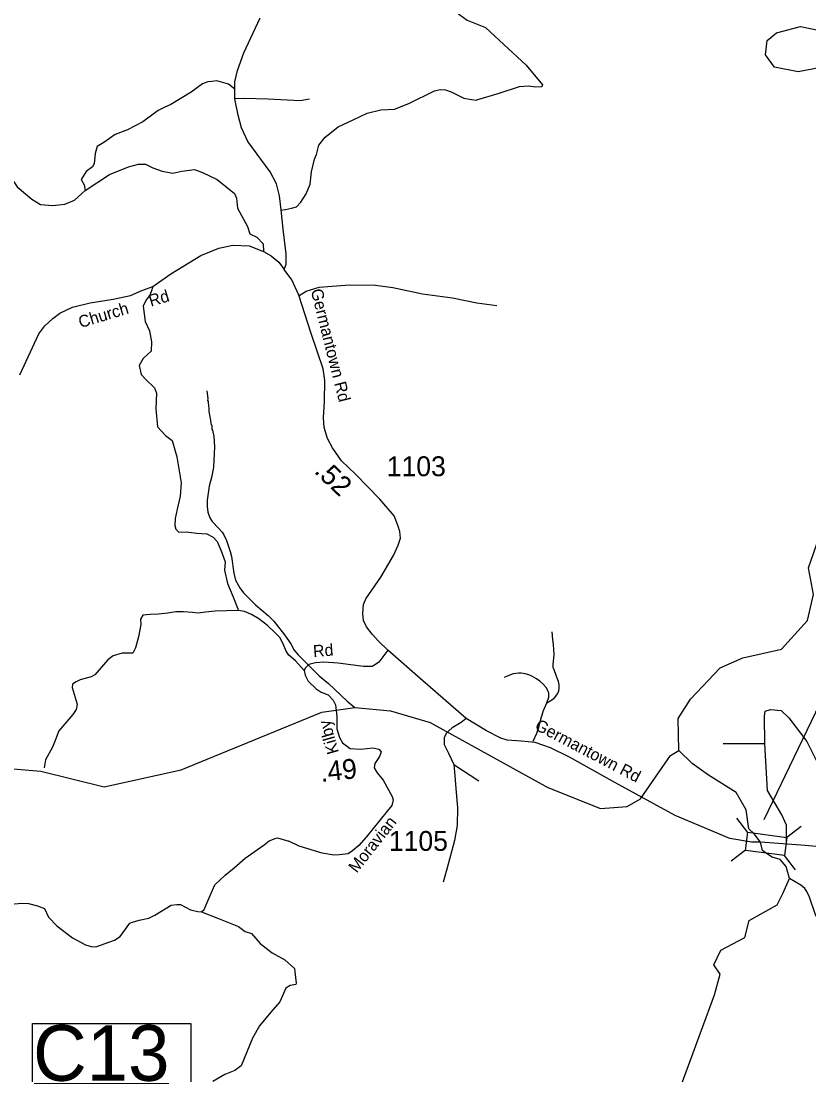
# Model space of a CAD drawing. Extents: x 1248089 to 1457196, y 820910 to 988753.
# Drawn here: x 1345980 to 1350937, y 860169 to 866798 of the extents above; entities that cross this region are included whole.
import ezdxf

# ---------------------------------------------------------------- set-up
doc = ezdxf.new("R2010")
doc.units = 0
for name, color, linetype in [('Exist Hydrographic Creek Single Shore', 7, 'Continuous'), ('Exist Hydrographic Misc Water Feature', 7, 'Continuous'), ('Exist Road Non-System Type 51', 7, 'Continuous'), ('Exist Road Primary NC Structure Culvert Number Label', 7, 'Continuous'), ('Exist Road Secondary Structure Standard Bridge CELL', 7, 'Continuous'), ('Exist Road Secondary Structure Standard Bridge Number Label', 7, 'Continuous'), ('Exist Road Secondary Type 51 Attributed', 7, 'Continuous'), ('Exist Road Secondary Type 51 Label', 7, 'Continuous'), ('Prop GRAU CAT1 Cell', 7, 'Continuous'), ('Prop Lane Lines', 7, 'Continuous')]:
    doc.layers.add(name, color=color, linetype=linetype)

msp = doc.modelspace()

# ---------------------------------------------------------------- linework, layer by layer
at = {"layer": 'Exist Hydrographic Creek Single Shore'}
for points in [[(1351155.2, 866532.2), (1350870.2, 866478.7), (1350721.2, 866508.1), (1350664.2, 866584.8), (1350675.2, 866676.4), (1350734.2, 866724.5), (1350885.2, 866764.1), (1351109.2, 866716.9)], [(1350118.3, 862209.9), (1350114.3, 862410.2), (1350191.3, 862533.3), (1350379.2, 862729.8), (1350522.2, 862792.6), (1350765.2, 862846.9), (1350928.2, 863027.4), (1350965.2, 863190.7), (1350935.2, 863358.9), (1351033.2, 863642.5), (1351023.3, 863951.2), (1351111.2, 864139.8), (1351122.2, 864632), (1351031.3, 865067.3)], [(1350632.1, 861633.8), (1350592.8, 861685), (1350559, 861717), (1350543.5, 861836.7), (1350479.8, 861945.6), (1350306.2, 862055.1), (1350202.8, 862128.4), (1350118.3, 862209.9)], [(1350010.2, 859554.6), (1350015.3, 859784.7), (1350342.3, 860672.3), (1350378.3, 860802.8), (1350338.3, 860862.8), (1350382.3, 860953.7), (1350534.2, 861032.8), (1350561.3, 861140.6), (1350738.3, 861238.7), (1350773.3, 861310.3), (1350816.1, 861404.3), (1350793.7, 861479.4), (1350757.2, 861524.2), (1350706.1, 861539.7), (1350669.5, 861561.6), (1350644.9, 861581.7), (1350632.1, 861633.8)]]:
    msp.add_lwpolyline(points, dxfattribs=at)
at = {"layer": 'Exist Hydrographic Misc Water Feature'}
for points in [[(1347148.6, 864472.9), (1347155.6, 864424.8), (1347153.2, 864410.9), (1347157.1, 864404.7), (1347158.4, 864372.8), (1347162.2, 864364.7), (1347161.7, 864342.6), (1347172.5, 864288.4), (1347173.9, 864266.3), (1347179.7, 864252.2), (1347181.2, 864230.2), (1347185, 864224.1), (1347192.1, 864183.9), (1347196.7, 864119.8), (1347189.7, 863992.1), (1347180.5, 863936.3), (1347163.1, 863872.6), (1347151.1, 863785), (1347150.2, 863745), (1347155.4, 863708.9), (1347166.6, 863672.6), (1347182, 863650.3), (1347225.1, 863607.2), (1347244.5, 863582.8), (1347256.2, 863566.5), (1347273.3, 863530.1), (1347295.7, 863461.6), (1347303, 863429.4), (1347318.7, 863325), (1347329.7, 863280.8), (1347356.6, 863232.2), (1347379.9, 863201.6), (1347454.2, 863125.8), (1347534.7, 863059.9), (1347569.9, 863023.1), (1347638, 862937.5), (1347676.7, 862880.6), (1347697.8, 862842), (1347723.2, 862811.5), (1347856.2, 862680.4), (1347915.1, 862630.9), (1348032.6, 862520.1), (1348080.4, 862480.3)], [(1343252.1, 861711), (1343773.1, 861858), (1344244.2, 862055.4), (1344470.1, 862109.9), (1344769.2, 862028.4), (1344958.1, 861932.7), (1345133.2, 861935.7), (1345929.2, 862093.7), (1346104.2, 862080.4), (1346502.2, 861980.5), (1346988.2, 862088.9), (1347872.2, 862451.9), (1348080.4, 862480.3), (1348305.2, 862459.6), (1348554.2, 862385.7), (1349295.2, 861976.8), (1349626.3, 861845.5), (1349793.3, 861858.5), (1349877.2, 861906.1), (1350067.2, 862178.1), (1350118.3, 862209.9)], [(1351511.8, 860340.9), (1351387.2, 860478.5), (1351340.2, 860521.7), (1351298.9, 860552.6), (1351247.9, 860599.8), (1351234.3, 860616.2), (1351211.2, 860656.7), (1351203.9, 860688.9), (1351177.2, 860745.5), (1351134.5, 860802.5), (1351111, 860827.1), (1351080.3, 860883.8), (1351076.7, 860899.9), (1351055.8, 860948.4), (1351030.6, 861069), (1350977, 861182.3), (1350941.5, 861287), (1350924.2, 861323.4), (1350910.7, 861341.8), (1350887.1, 861362.3), (1350816.1, 861404.3)]]:
    msp.add_lwpolyline(points, dxfattribs=at)
at = {"layer": 'Exist Road Non-System Type 51'}
msp.add_line((1350660.7, 862252.6), (1350398.6, 862252.3), dxfattribs=at)
for points in [[(1348355.8, 867250.9), (1348534.7, 867008.8), (1348648.8, 866904.8), (1348786.8, 866804.2), (1348902.7, 866758.2), (1349018.5, 866650.7), (1349158.2, 866519.5), (1349260.4, 866397.6), (1349257, 866383.9), (1349219.5, 866382.2), (1349171.8, 866389.1), (1349113.9, 866383.9), (1348986.1, 866341.3), (1348846.4, 866300.4)], [(1347325.4, 866369), (1347286, 866400.1), (1347211.6, 866421.8), (1347180.6, 866418.7), (1347155.7, 866415.6), (1347121.6, 866403.2), (1347050.3, 866350.5), (1346923.2, 866272.9), (1346879.8, 866254.3), (1346842.5, 866235.6), (1346746.4, 866164.3), (1346650.3, 866114.6), (1346572.7, 866083.6), (1346501.4, 866033.9), (1346458, 866009.1), (1346445.6, 865965.6), (1346439.4, 865900.5), (1346430.1, 865881.9), (1346389.8, 865850.8), (1346358.8, 865801.2), (1346377.4, 865767), (1346383.6, 865732.9)], [(1347613.1, 865608.2), (1347643.7, 865611.6), (1347681.2, 865621.9), (1347711.9, 865628.7), (1347740.8, 865659.4), (1347773.2, 865710.5), (1347798.8, 865771.9), (1347807.3, 865850.3), (1347826, 865928.7), (1347839.6, 865959.4), (1347853.3, 866017.4), (1347894.1, 866068.5), (1347975.9, 866131.6), (1348069.6, 866175.9), (1348158.2, 866218.6), (1348243.4, 866239), (1348328.6, 866244.1), (1348418.8, 866279.1), (1348580.7, 866359.2), (1348616.5, 866367.7), (1348650.5, 866366), (1348686.3, 866352.4), (1348766.4, 866313.2), (1348814.1, 866304.7), (1348846.4, 866300.4)], [(1345772.4, 866332.4), (1345735.2, 866195.9), (1345713.5, 866087.3), (1345722.8, 866037.6), (1345766.2, 865984.9), (1345859.2, 865898), (1345955.3, 865755.2), (1346048.4, 865677.6), (1346101.1, 865643.5), (1346178.6, 865637.3), (1346256.1, 865646.6), (1346315.1, 865671.4), (1346383.6, 865732.9)], [(1347325.2, 866309.8), (1347384.8, 866313.2), (1347534.7, 866308.1), (1347735.7, 866297.8), (1347795.3, 866308.1)], [(1346383.6, 865732.9), (1346535.5, 865832.2), (1346656.5, 865881.9), (1346718.5, 865897.4), (1346761.9, 865897.4), (1346808.4, 865875.6), (1346867.3, 865853.9), (1346935.6, 865841.5), (1346991.4, 865853.9), (1347072, 865863.2), (1347121.6, 865844.6), (1347214.7, 865801.2), (1347323.2, 865714.3), (1347335.6, 865683.2), (1347341.8, 865621.2), (1347403.8, 865506.4), (1347419.3, 865459.8), (1347462.8, 865438.1), (1347503.1, 865397.7), (1347505.1, 865348.1)], [(1346809.1, 865128.1), (1346797.8, 865093.9), (1346788.5, 865069.1), (1346766.8, 865044.2), (1346748.2, 865003.9), (1346760.6, 864907.7), (1346788.5, 864848.7), (1346800.9, 864780.5), (1346797.8, 864721.5), (1346776.1, 864699.8), (1346748.2, 864674.9), (1346723.4, 864631.5), (1346735.8, 864575.6), (1346763.7, 864544.6), (1346819.5, 864491.9), (1346832, 864457.7), (1346828.8, 864358.4), (1346838.2, 864246.7), (1346887.8, 864190.8), (1346931.2, 864159.8), (1346959.1, 864057.4), (1346987, 863892.9), (1346980.8, 863809.1), (1346962.2, 863728.4), (1346949.8, 863669.5), (1346946.7, 863626), (1346952.9, 863601.2), (1346971.5, 863582.6), (1347018, 863585.7), (1347086.2, 863576.4), (1347148.3, 863573.3), (1347188.6, 863551.6), (1347213.4, 863524.7), (1347238.2, 863466.7), (1347265.1, 863396.4), (1347260.9, 863344.7), (1347279.5, 863259.8), (1347312.6, 863181.2), (1347347.6, 863090.6)], [(1347728.9, 865071.2), (1347773.2, 865098.5), (1347855, 865124), (1348045.8, 865139.4), (1348211, 865136), (1348320, 865122.3), (1348505.7, 865081.4), (1348694.8, 865057.6), (1348848.1, 865025.2), (1348972.5, 865008.1)], [(1347347.6, 863090.6), (1347200.8, 863086.4), (1347140.9, 863080.2), (1347093.3, 863074), (1347058.2, 863078.1), (1347002.4, 863082.3), (1346952.7, 863082.3), (1346903.1, 863074), (1346845.2, 863067.8), (1346791.5, 863065.7), (1346746, 863061.6), (1346732.1, 863035.1), (1346734.2, 863002), (1346719.7, 862925.5), (1346699, 862855.1), (1346682.5, 862822), (1346616.3, 862822), (1346558.5, 862805.5), (1346525.4, 862780.7), (1346444.8, 862685.5), (1346419.9, 862673.1), (1346351.7, 862654.5), (1346326.9, 862642), (1346304.2, 862627.6), (1346302.1, 862606.9)], [(1347760.2, 862713.2), (1347707.3, 862774), (1347663.9, 862809.2), (1347647.4, 862834), (1347628.8, 862881.6), (1347608.1, 862920.9), (1347577.1, 862951.9), (1347529.5, 862995.4), (1347475.8, 863038.8), (1347430.3, 863065.7), (1347384.8, 863084.3), (1347347.6, 863090.6)], [(1349288.4, 862508.9), (1349318.8, 862528.3), (1349339.1, 862543.9), (1349355.6, 862565.6), (1349364, 862585.4), (1349366.4, 862603.4), (1349364.8, 862623.4), (1349361.2, 862643.5), (1349353.6, 862665.7), (1349345.9, 862681.8), (1349334.6, 862718.1), (1349328.9, 862732.2), (1349327.3, 862750.2), (1349329.7, 862770.2), (1349334.6, 862814.1), (1349333.1, 862842.2), (1349329.8, 862876.3), (1349326.5, 862908.4), (1349321.4, 862956.5)], [(1349288.4, 862508.9), (1349301.1, 862544.6), (1349301.5, 862560.7), (1349299.7, 862570.7), (1349294, 862586.8), (1349284.4, 862607), (1349264.8, 862627.4), (1349243.1, 862645.9), (1349223.4, 862660.3), (1349193.7, 862676.9), (1349175.9, 862685.2), (1349152, 862691.7), (1349126.1, 862696.3), (1349110.1, 862696.6), (1349075.9, 862691.3), (1349037.7, 862678), (1349019.4, 862668.4)], [(1346302.1, 862606.9), (1346333.6, 862501.9), (1346327.4, 862468.8), (1346304.6, 862435.7), (1346217.8, 862334.4), (1346195.1, 862272.3), (1346176.5, 862230.9), (1346133.1, 862150.2), (1346124.8, 862100.6)], [(1349201.5, 862268.5), (1349224.5, 862318.1), (1349237.3, 862353.8), (1349248.1, 862397.6), (1349254.6, 862421.5), (1349267.4, 862461.3), (1349288.4, 862508.9)], [(1350660.7, 862252.6), (1350657.9, 862426.4), (1350661.3, 862457.2), (1350695.4, 862467.4), (1350763.6, 862460.6), (1350811.4, 862416.2), (1350923.9, 862266), (1350999, 862115.8), (1351046.7, 862085.1), (1351125.2, 862095.3), (1351203.7, 862109), (1351640.3, 862126)], [(1348779.6, 862411.3), (1348748.3, 862385), (1348692.5, 862351.8), (1348671.8, 862333.2), (1348655.3, 862316.7), (1348642.9, 862289.8), (1348642.9, 862248.4), (1348669.8, 862192.5), (1348702.9, 862122.2)], [(1350797.1, 861621), (1350797.1, 861740.5), (1350766.4, 861805.4), (1350677.7, 861959), (1350660.7, 862252.6)], [(1348702.9, 862122.2), (1348709.1, 862049.8), (1348717.3, 861946.4), (1348725.6, 861851.2), (1348723.5, 861737.4), (1348707, 861644.3), (1348659.2, 861463.8), (1348636.4, 861381)], [(1348702.9, 862122.2), (1348860, 862018.8)], [(1347320.6, 861472.1), (1347388.9, 861532.1), (1347508.8, 861617), (1347541.8, 861641.8), (1347579.1, 861656.3), (1347593.5, 861660.4)], [(1347593.5, 861660.4), (1347664.9, 861639.4)], [(1345917.6, 861243.1), (1345981.7, 861249.3), (1346027.2, 861247.2), (1346083, 861232.7), (1346126.4, 861216.2), (1346153.3, 861162.4), (1346205, 861106.5), (1346304.2, 861032.1), (1346384.8, 860988.6), (1346420, 860976.2), (1346451, 860974.1), (1346566.8, 861017.6), (1346604, 861040.3), (1346663.9, 861123.1), (1346680.5, 861129.3), (1346723.9, 861141.7), (1346783.8, 861156.2), (1346821, 861174.8), (1346924.4, 861236.9), (1346959.6, 861241), (1346982.3, 861241), (1347046.4, 861207.9), (1347091.9, 861197.6), (1347116, 861194.9), (1347132.5, 861209.4), (1347169.7, 861298.4), (1347198.7, 861364.6), (1347264.8, 861426.6), (1347320.6, 861472.1)], [(1347116, 861194.9), (1347221.4, 861153.8), (1347347.5, 861102.1), (1347388.9, 861071), (1347430.2, 861058.6), (1347484, 860996.6), (1347560.5, 860936.6), (1347639, 860893.1), (1347701.1, 860839.3), (1347703.1, 860818.6), (1347711.4, 860746.2), (1347709.3, 860737.9), (1347672.1, 860731.7), (1347645.2, 860715.2), (1347608, 860628.3), (1347552.2, 860564.2), (1347479.8, 860477.3), (1347436.5, 860400.2), (1347364.2, 860226.4), (1347324.9, 860197.4), (1347262.9, 860172.6), (1347186.4, 860127.1)]]:
    msp.add_lwpolyline(points, dxfattribs=at)
at = {"layer": 'Exist Road Primary NC Structure Culvert Number Label'}
msp.add_lwpolyline([(1346051.9, 860492.4), (1347047.3, 860492.4), (1347047.3, 860112.5), (1346051.9, 860112.5)], close=True, dxfattribs=at)
at = {"layer": 'Exist Road Secondary Structure Standard Bridge CELL'}
for p, q in [((1350553.1, 861694.4), (1350484.4, 861784.3)), ((1350889, 861732.5), (1350799.1, 861663.7)), ((1350538.2, 861582.2), (1350448.3, 861513.4)), ((1350852.6, 861459), (1350783.8, 861548.9))]:
    msp.add_line(p, q, dxfattribs=at)
msp.add_lwpolyline([(1350783.8, 861548.9), (1350538.1, 861581.7), (1350553.4, 861696.4), (1350799.1, 861663.7)], close=True, dxfattribs=at)
at = {"layer": 'Exist Road Secondary Structure Standard Bridge Number Label'}
msp.add_line((1350655.5, 861776.7), (1351747.8, 864049.4), dxfattribs=at)
at = {"layer": 'Exist Road Secondary Type 51 Attributed'}
for points in [[(1347635.1, 865235.8), (1347648.6, 865268.2), (1347648.6, 865333), (1347629.7, 865489.7), (1347616, 865609.5), (1347605.4, 865697.8), (1347586.5, 865773.4), (1347546.7, 865850.3), (1347406.3, 866039.4), (1347365.8, 866125.9), (1347346.9, 866206.9), (1347325.4, 866309.6), (1347325.4, 866415), (1347341.6, 866487.9), (1347382, 866598.7), (1347483.4, 866818.8)], [(1345971.3, 864572.2), (1346092.2, 864830.1), (1346129.2, 864880.6), (1346179.7, 864926.1), (1346223.5, 864961.4), (1346302.6, 864998.5), (1346415.3, 865025.4), (1346558.3, 865049), (1346669.4, 865070.9), (1346740.1, 865102.9), (1346809.1, 865128.1), (1346921.8, 865207.3), (1347111.2, 865322.8), (1347224, 865369.9), (1347311.5, 865388.5), (1347414.1, 865383.4), (1347505.1, 865348.1), (1347553.8, 865321.1), (1347601.9, 865280.9), (1347635.1, 865235.8)], [(1348286.9, 862840.9), (1348229.1, 862896.8), (1348188.2, 862942), (1348153.8, 862987.2), (1348134.4, 863028.1), (1348130.1, 863071.2), (1348134.4, 863127.2), (1348149.5, 863163.8), (1348243.9, 863300.4), (1348323.5, 863436.1), (1348353.6, 863500.7), (1348366.5, 863545.9), (1348362.2, 863586.8), (1348353.6, 863621.3), (1348327.8, 863685.9), (1348237.8, 863790.6), (1348085, 863947.8), (1347996.8, 864031.8), (1347938.7, 864113.7), (1347908.6, 864171.8), (1347887.1, 864240.7), (1347882.8, 864303.2), (1347889.2, 864405.3), (1347891.4, 864536.7), (1347880.6, 864609.9), (1347805.3, 864831.7), (1347727.8, 865072.9), (1347682.7, 865169.8), (1347635.1, 865235.8)], [(1348286.9, 862840.9), (1348231.4, 862764.9), (1348209.9, 862749.9), (1348188.4, 862739.1), (1348134.6, 862739.1), (1347975.4, 862758.5), (1347885, 862764.9), (1347833.4, 862760.6), (1347790.3, 862749.9), (1347766.6, 862728.3), (1347760.2, 862713.2), (1347766.6, 862683.1), (1347786, 862646.5), (1347837.7, 862597), (1347867.8, 862577.6), (1347913, 862560.3), (1347943.1, 862525.9), (1347958.2, 862497.9), (1347966.8, 862424.7), (1347966.8, 862347.2), (1347984, 862291.2), (1348003.3, 862258.9), (1348050.7, 862222.2), (1348115.2, 862217.9), (1348194.9, 862226.6), (1348231.1, 862218.7), (1348246.2, 862201.5), (1348235.4, 862171.3), (1348205.3, 862128.2), (1348201, 862100.2), (1348220.4, 862070.1), (1348259.1, 862022.7), (1348315, 861921.5), (1348321.6, 861898.6), (1348313, 861864.2), (1348282.8, 861827.6), (1348151.6, 861663.9), (1348104.2, 861612.2), (1348065.5, 861577.8), (1348037.5, 861560.5), (1347981.6, 861554.1), (1347947.2, 861551.9), (1347874, 861564.8), (1347729.8, 861607.9), (1347664.9, 861639.4)], [(1350632.1, 861633.8), (1350575.5, 861632.5), (1350440.6, 861656.9), (1350095.8, 861800.6), (1349715.8, 862008.2), (1349431, 862167.6), (1349312.2, 862227.1), (1349215, 862260.8), (1349127.3, 862268.9), (1349038.2, 862275.7), (1348999.1, 862286.5), (1348909.2, 862332.9), (1348779.6, 862411.3), (1348508.3, 862649), (1348286.9, 862840.9)], [(1351118.1, 861593.4), (1350913, 861612.3), (1350632.1, 861633.8)]]:
    msp.add_lwpolyline(points, dxfattribs=at)

# ---------------------------------------------------------------- texts
at = {"layer": 'Exist Road Primary NC Structure Culvert Number Label'}
msp.add_text('C13', height=350, dxfattribs=at).set_placement((1346055.1, 860132.3))
at = {"layer": 'Exist Road Secondary Type 51 Label'}
for s, rotation, p in [(' Church     Rd', 16.84749, (1346327.2, 864858.2)), ('Germantown Rd', 284.1931, (1347801.9, 865103.9)), ('Rd', 4.31499, (1347819.8, 862797.1)), ('Kilby ', 105.88522, (1347980.8, 862198.7)), ('Germantown Rd', 332.36779, (1349206.7, 862344.8)), ('Moravian', 51.74313, (1348092.1, 861434.6))]:
    msp.add_text(s, height=75, rotation=rotation, dxfattribs=at).set_placement(p)
at = {"layer": 'Prop GRAU CAT1 Cell'}
for s, rotation, p in [('.52', 316.40946, (1347819, 863960.6)), ('.49', 6.17494, (1347868, 862011.6))]:
    msp.add_text(s, height=125, rotation=rotation, dxfattribs=at).set_placement(p)
at = {"layer": 'Prop Lane Lines'}
for s, p in [('1103', (1348280.8, 863935.3)), ('1105', (1348294.1, 861578.6))]:
    msp.add_text(s, height=125, dxfattribs=at).set_placement(p)

doc.saveas('drawing.dxf')
